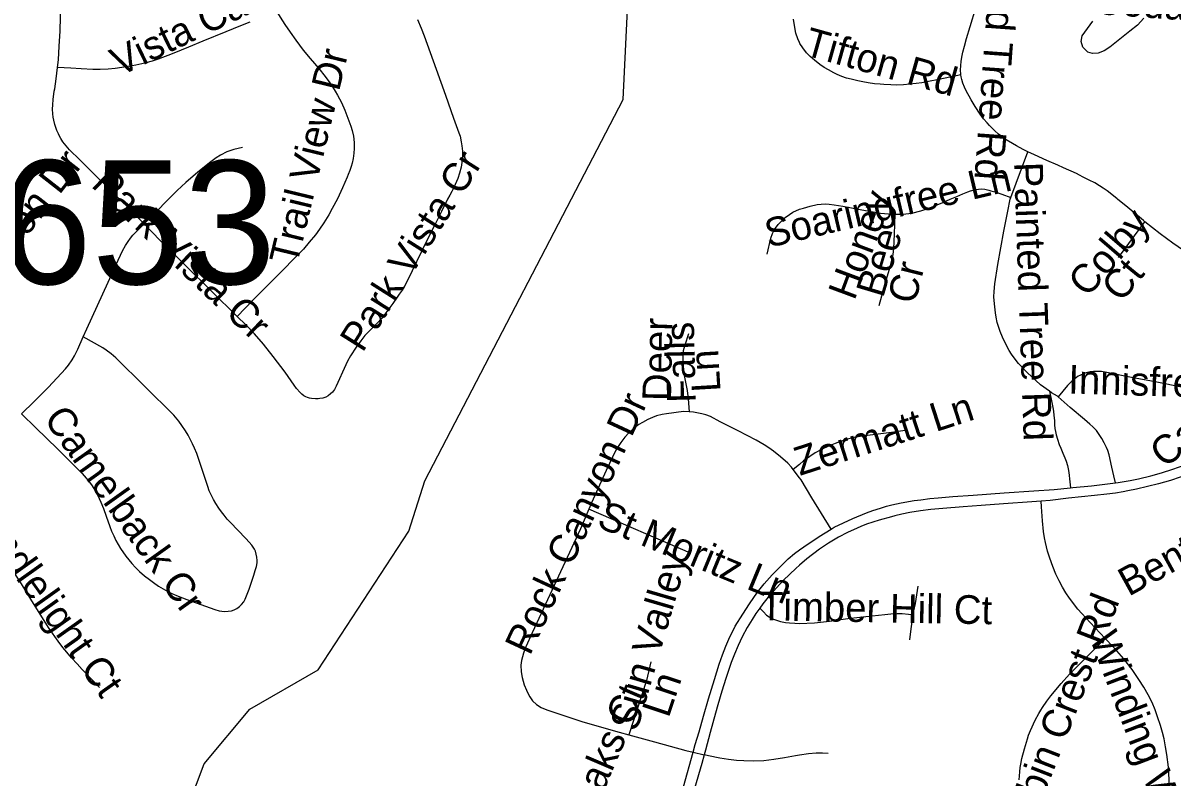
# Model space of a CAD drawing. Extents: x 1383679 to 1536984, y 460658 to 651027.
# Drawn here: x 1441502 to 1445312, y 487151 to 489649 of the extents above; entities that cross this region are included whole.
import ezdxf

# ---------------------------------------------------------------- set-up
doc = ezdxf.new("R2010")
doc.units = 0
for name, color, linetype in [('Exist Hydrographic Creek Single Shore', 7, 'Continuous'), ('Exist Road Non-System Type 51', 7, 'Continuous'), ('Exist Road Non-System Type 51 Label', 7, 'Continuous'), ('Exist Road Primary US Structure Non-Sys NCDOT Number Label', 7, 'Continuous')]:
    doc.layers.add(name, color=color, linetype=linetype)

msp = doc.modelspace()

# ---------------------------------------------------------------- linework, layer by layer
at = {"layer": 'Exist Hydrographic Creek Single Shore'}
msp.add_lwpolyline([(1440714.2, 484403.2), (1441192.2, 484968), (1441297.1, 485235.1), (1441297.1, 485676.3), (1441341, 485777.5), (1441756.5, 486277.7), (1442102.4, 487194.6), (1442253.2, 487375.7), (1442480.2, 487505.7), (1442780.2, 487965.7), (1442833.2, 488132.1), (1443490.2, 489395.8), (1443517.3, 489946.6)], dxfattribs=at)
at = {"layer": 'Exist Road Non-System Type 51'}
for p, q in [((1444774.5, 489071.2), (1444831.6, 489222.1)), ((1445131.9, 488872.3), (1445219.4, 488990.4)), ((1443713.5, 487892.8), (1443376.4, 488038.1)), ((1443722.7, 487233), (1443758.7, 487224.3))]:
    msp.add_line(p, q, dxfattribs=at)
for points in [[(1441616.1, 489501.8), (1441619, 489526.9), (1441622, 489572.1), (1441624.8, 489622.1), (1441625.6, 489669.8), (1441624.7, 489728.7), (1441623.3, 489767.8), (1441622.8, 489805.8), (1441620.1, 489834.7)], [(1444609.1, 489477.5), (1444608.8, 489479.5), (1444608.1, 489493.2), (1444608.8, 489508.6), (1444610.2, 489521.5), (1444612.7, 489535.6), (1444616.3, 489553.1), (1444621.4, 489572.9), (1444628.2, 489597.7), (1444640, 489638.2), (1444696.9, 489824.2), (1444709.2, 489868.5)], [(1442340.8, 489690.1), (1442369.2, 489644.9), (1442386.9, 489619), (1442405.7, 489592.4), (1442430.7, 489559), (1442453.4, 489531.9), (1442482.1, 489499), (1442503.5, 489472.3), (1442518.5, 489451), (1442527.3, 489437.6), (1442535.7, 489423.6), (1442544.1, 489409.8), (1442556.8, 489385.7), (1442568.1, 489360.6), (1442578.7, 489333.6), (1442588.3, 489307.7), (1442592.8, 489292.9), (1442596.6, 489274.5), (1442598.8, 489253.1), (1442599.4, 489233.2), (1442598.6, 489217.7), (1442596.3, 489200.3), (1442592.8, 489184.7), (1442589.3, 489173.8), (1442584.4, 489160.7), (1442579.6, 489147.8), (1442576.1, 489138.5), (1442560.9, 489103.6), (1442543.4, 489066.5), (1442526.5, 489034.2), (1442515.1, 489013.8), (1442498.3, 488987.7), (1442484.6, 488966.7), (1442470.7, 488947.6), (1442450.5, 488922.6), (1442431.2, 488900.2), (1442409.6, 488878), (1442353.5, 488821.5), (1442326, 488794.2), (1442301.4, 488768), (1442265, 488731.7), (1442212, 488677.3)], [(1442254, 489652), (1442222.6, 489639.7), (1442173.9, 489620.1), (1442097.9, 489589.4), (1442050.1, 489569.2), (1442002.1, 489549.4), (1441981.4, 489541.1), (1441964.2, 489534.8), (1441949.5, 489529.4), (1441929.5, 489523.2), (1441909, 489517.7), (1441895.2, 489514.1), (1441875.9, 489509.7), (1441863.7, 489507.4), (1441843.4, 489503.7), (1441828.8, 489501.5), (1441807.2, 489499), (1441784.4, 489496.8), (1441757.5, 489495.6), (1441733.3, 489495.6), (1441694.8, 489497), (1441660.6, 489499.4), (1441616.1, 489501.8)], [(1442809.2, 489660.7), (1442821.2, 489631.8), (1442831.4, 489606.8), (1442871.1, 489496.9), (1442901.9, 489410.7), (1442928, 489334.3), (1442941.8, 489297.6), (1442946, 489285.4), (1442949.9, 489273.9), (1442954.1, 489255.3), (1442956, 489241.8), (1442957.7, 489224.5), (1442958.1, 489209.8), (1442956.8, 489197.2), (1442955.7, 489187.4), (1442953.4, 489171.3), (1442948.3, 489151.6), (1442942.3, 489133.7), (1442934.3, 489114.7), (1442928.6, 489102.4), (1442922.5, 489091.2), (1442916.1, 489079.2), (1442908.8, 489066), (1442888.7, 489025), (1442864, 488976), (1442836.2, 488922.4), (1442775.8, 488795.7), (1442763.6, 488773.3), (1442758.1, 488764.3), (1442748.4, 488750.4), (1442727.2, 488720.3), (1442701.3, 488684.7), (1442689.2, 488670.4), (1442675.5, 488655.1), (1442645.6, 488625.2), (1442634.7, 488613.3), (1442620.8, 488595.7), (1442605.9, 488574.7), (1442587, 488546.6), (1442576.8, 488529.2), (1442571.4, 488516.9), (1442539, 488446.2), (1442534.2, 488435.3), (1442527.6, 488426.3), (1442520.5, 488420.3), (1442513.3, 488414.3), (1442504.9, 488409.3), (1442495.6, 488406.2), (1442485.8, 488404.6), (1442479.4, 488404.3), (1442471.3, 488404.3), (1442458.2, 488405.5), (1442450.7, 488406.6), (1442444.9, 488408.8), (1442438.7, 488411), (1442432.4, 488414), (1442426, 488419.3), (1442419.9, 488425.3), (1442407.9, 488438.6), (1442400.4, 488449), (1442370.5, 488492.7), (1442331.3, 488544.2), (1442298.6, 488585.4), (1442268.9, 488619.2), (1442240.2, 488649.5), (1442212, 488677.3)], [(1444609.1, 489477.5), (1444536.6, 489462), (1444502.3, 489455.4), (1444479.7, 489451.6), (1444460.9, 489448.5), (1444440.7, 489446.2), (1444419, 489444.7), (1444397.6, 489443.7), (1444377.9, 489444), (1444354.5, 489445.1), (1444342, 489446.2), (1444322.9, 489448), (1444302.4, 489450.8), (1444284.8, 489454.1), (1444268.3, 489457.3), (1444246.4, 489462.7), (1444231, 489467), (1444215.2, 489472.4), (1444199.4, 489478.8), (1444188.6, 489483.9), (1444170.6, 489493.6), (1444156.3, 489502.2), (1444141.6, 489512.2), (1444124.3, 489525.9), (1444109.9, 489538.8), (1444098.4, 489550.5), (1444085.6, 489567), (1444076.1, 489581.9), (1444075, 489584.3), (1444069.2, 489596.9), (1444062.6, 489616.2), (1444057.7, 489641.6), (1444054.5, 489661.5)], [(1445216.1, 489665.8), (1445194.2, 489642.4), (1445169.5, 489622.8), (1445103.2, 489569.4), (1445083.8, 489556.7), (1445064.1, 489549.2), (1445045.4, 489548.4), (1445029.6, 489552.9), (1445013.8, 489569.4), (1445007.8, 489588.2), (1445010.8, 489606.3), (1445046.5, 489655.9)], [(1441903.1, 488983.9), (1441855.8, 489032.8), (1441822, 489066), (1441804.8, 489082.9), (1441742.6, 489143.8), (1441732.4, 489153.7), (1441690.3, 489195.8), (1441655.9, 489229.5), (1441639.5, 489248.8), (1441634.2, 489255.9), (1441627.6, 489266.4), (1441623.1, 489274.7), (1441619.4, 489282.2), (1441614.4, 489292.6), (1441611.5, 489299.6), (1441607.1, 489313.3), (1441604, 489327.5), (1441602.2, 489337), (1441600.9, 489348.3), (1441599.6, 489364.3), (1441600.3, 489378.6), (1441601.7, 489395.5), (1441605.6, 489423.8), (1441606.9, 489431.7), (1441611.7, 489464.2), (1441616.1, 489501.8)], [(1444831.6, 489222.1), (1444816.1, 489230), (1444793.4, 489241.9), (1444780.1, 489249.8), (1444760, 489262.7), (1444748.5, 489271), (1444734.5, 489281.4), (1444722.3, 489291.8), (1444710.8, 489302.9), (1444704.3, 489309.4), (1444696.1, 489318.4), (1444684.9, 489331.3), (1444673.1, 489347.4), (1444656.9, 489372.6), (1444644, 489394.8), (1444636.4, 489407.4), (1444628.5, 489422.1), (1444621.4, 489436.5), (1444616, 489450.5), (1444612.4, 489462), (1444610.2, 489470.6), (1444609.1, 489477.5)], [(1442228.8, 489237.1), (1442200.9, 489230.7), (1442177.3, 489222.1), (1442156.7, 489211.8), (1442141.8, 489202.7), (1442119.8, 489185.8), (1442081.3, 489154.9), (1442040.9, 489120.3), (1442012.5, 489094.5), (1441984.3, 489066), (1441971.7, 489053.3), (1441951.5, 489032.7), (1441903.1, 488983.9)], [(1445219.4, 488990.4), (1445214.1, 488994.6), (1445162.3, 489038.4), (1445128.6, 489066), (1445125.8, 489068.3), (1445094.2, 489092.9), (1445081.2, 489102.2), (1445068.6, 489110.1), (1445052.9, 489119.4), (1445034.8, 489129), (1445014.9, 489138.7), (1445002.1, 489145.4), (1444992.7, 489150.1), (1444949.8, 489169.3), (1444930.6, 489178.1), (1444894.6, 489193.8), (1444853.5, 489212.2), (1444831.6, 489222.1)], [(1444391.3, 489015.6), (1444391.4, 489015.6), (1444412.8, 489015.9), (1444427.1, 489016.8), (1444446.7, 489019.5), (1444476.7, 489026.6), (1444501.4, 489034.7), (1444549.3, 489054.3), (1444574.1, 489066), (1444596.3, 489074.8), (1444615.8, 489082.9), (1444632.2, 489089.4), (1444641.8, 489092.9), (1444657.6, 489097.2), (1444667.8, 489098.7), (1444677.7, 489099.3), (1444688.5, 489098.7), (1444697.3, 489096.9), (1444702.5, 489095.5), (1444708.7, 489093.7), (1444721.5, 489089.9), (1444745.2, 489082.3), (1444774.5, 489071.2)], [(1443967.4, 488883.4), (1443979.5, 488936.1), (1443984.8, 488951.7), (1443991.5, 488965.3), (1444003.7, 488981.2), (1444015.7, 488994.1), (1444027.7, 489005.2), (1444041.4, 489015.1), (1444052.6, 489022.1), (1444075, 489032.7), (1444087.9, 489036.3), (1444110.6, 489042.4), (1444133.1, 489047.5), (1444146.9, 489049.2), (1444160.5, 489049.8), (1444173.4, 489049), (1444190, 489047), (1444218.1, 489042.1), (1444281.7, 489029.8), (1444343.1, 489019.7), (1444369.1, 489016.8), (1444391.3, 489015.6)], [(1444902.8, 488428.8), (1444873.4, 488450.7), (1444828.9, 488491.7), (1444800.9, 488520.9), (1444785.5, 488540), (1444777, 488552.1), (1444769.5, 488563.6), (1444759, 488583), (1444747.6, 488608.2), (1444739.6, 488627), (1444734.1, 488643.7), (1444730.2, 488656.5), (1444726.3, 488674.7), (1444724.2, 488688.5), (1444720.5, 488718.8), (1444719, 488742.4), (1444719.5, 488759.2), (1444722.1, 488785.2), (1444731.4, 488849.5), (1444752.2, 488959.4), (1444765.1, 489025.5), (1444772.5, 489066), (1444774.5, 489071.2)], [(1444338.8, 488713.3), (1444360.1, 488789.8), (1444375.7, 488841.1), (1444381.1, 488863.5), (1444384.7, 488882.6), (1444386.9, 488902.5), (1444389.1, 488949.4), (1444391.3, 489015.6)], [(1441701.6, 488609.3), (1441713.2, 488635.9), (1441748.7, 488713.4), (1441783.8, 488790.7), (1441809, 488846.6), (1441824.8, 488880.1), (1441831.6, 488894.4), (1441842, 488912.3), (1441850.3, 488925.7), (1441858, 488936.1), (1441865.7, 488946.3), (1441869.6, 488950.1), (1441903.1, 488983.9)], [(1441903.1, 488983.9), (1441956.5, 488928.7), (1442212, 488677.3)], [(1445876.8, 488552.8), (1445846.9, 488574.5), (1445722.6, 488684.9), (1445681.9, 488720.1), (1445649.3, 488744.1), (1445620.3, 488762.4), (1445594, 488777.2), (1445552.9, 488797.4), (1445505.9, 488818.4), (1445423.1, 488854), (1445402.6, 488864.3), (1445383.1, 488874.5), (1445347, 488896), (1445311.5, 488920.1), (1445269.7, 488950.6), (1445219.4, 488990.4)], [(1443707.2, 488619.7), (1443694.8, 488581.9), (1443689.6, 488563.2), (1443688.4, 488552.2), (1443687.8, 488526.7), (1443689.2, 488506.9), (1443692.7, 488481.2), (1443702.2, 488432), (1443705.7, 488404.1), (1443709.1, 488361.3)], [(1441497.4, 488354), (1441539.1, 488394.7), (1441586.2, 488442.2), (1441643.2, 488502.8), (1441653.1, 488515.6), (1441665, 488532.7), (1441672.9, 488546), (1441683.9, 488568.6), (1441701.6, 488609.3)], [(1441497.4, 488354), (1441544.4, 488308.2), (1441616.2, 488238.4), (1441663.2, 488190.7), (1441697.8, 488156.3), (1441711.3, 488141.1), (1441721.9, 488127.6), (1441731.5, 488115.1), (1441740.4, 488101.6), (1441748.3, 488085.4), (1441753.7, 488073.8), (1441759.6, 488061.2), (1441768.1, 488040.3), (1441777.2, 488015.5), (1441789.2, 487980.5), (1441795, 487965.4), (1441802.3, 487950), (1441809.5, 487934.9), (1441825.2, 487907.8), (1441842.8, 487883.1), (1441862.5, 487858), (1441874.6, 487844.6), (1441887.9, 487831.6), (1441903.9, 487817.7), (1441920.7, 487804.8), (1441934.8, 487794.8), (1441950.6, 487783.4), (1441974.5, 487769.4), (1441994.9, 487758.9), (1442015.6, 487749.9), (1442044.2, 487738.5), (1442137.4, 487706), (1442151.7, 487701.7), (1442160.6, 487699.9), (1442169.9, 487699.6), (1442182.2, 487700.1), (1442192.4, 487701.7), (1442201.7, 487704.6), (1442210.9, 487709.6), (1442219.2, 487715.8), (1442226.2, 487722.3), (1442233.1, 487731), (1442238.3, 487740.2), (1442242.8, 487751), (1442250.8, 487773.6), (1442266.8, 487819.9), (1442271.5, 487835.5), (1442275.2, 487848.6), (1442277.5, 487860.4), (1442277.9, 487868.3), (1442276.7, 487879.1), (1442274.8, 487888.9), (1442272.1, 487899.1), (1442269.4, 487906.1), (1442264.8, 487912.8), (1442260.5, 487918.6), (1442241.6, 487940.2), (1442212.5, 487970.1), (1442190.9, 487992.6), (1442178.7, 488005.7), (1442168.3, 488017.9), (1442159.6, 488030), (1442151.2, 488041.8), (1442141.1, 488057.4), (1442133.6, 488070.1), (1442127.4, 488081.5), (1442119.1, 488099.6), (1442114.5, 488112.9), (1442087.5, 488193), (1442077.5, 488222.3), (1442070.2, 488241), (1442063.8, 488255.2), (1442056.1, 488270.3), (1442048.9, 488283.8), (1442040.3, 488298), (1442028.7, 488316), (1442018.1, 488329.9), (1442001.3, 488350.1), (1441809.6, 488539.8), (1441794.1, 488552.8), (1441777.7, 488564.9), (1441766.5, 488572.5), (1441701.6, 488609.3)], [(1445122, 488125.7), (1445130.2, 488126.7), (1445170.8, 488133.3), (1445198.4, 488139), (1445238.6, 488148.9), (1445274.7, 488158.8), (1445311.8, 488171.1), (1445348.8, 488184.5), (1445407.3, 488205), (1445458.6, 488225.5), (1445494, 488243), (1445526.1, 488260.7), (1445558.2, 488281.2), (1445589.8, 488302.7), (1445640.5, 488336.4), (1445658.2, 488348.7), (1445694.9, 488376.3), (1445718.8, 488396.3), (1445741.1, 488415.5), (1445789.1, 488461.7), (1445850.3, 488526.6), (1445876.8, 488552.8)], [(1445346, 488441.1), (1445252.8, 488459.9), (1445175.2, 488474.5), (1445093, 488491), (1445075.2, 488494), (1445058.5, 488495), (1445048.8, 488494.4), (1445038.1, 488493.1), (1445025, 488489.9), (1445015.9, 488486.8), (1445003.3, 488481.1), (1444998.5, 488478.5), (1444992.1, 488474.6), (1444984.5, 488469), (1444978.1, 488463.6), (1444963.3, 488448.3), (1444931.4, 488410.9)], [(1444931.4, 488410.9), (1444929.8, 488412.4), (1444909.7, 488423.7), (1444902.8, 488428.8)], [(1444902.8, 488428.8), (1444908.3, 488403.1), (1444914, 488375.4), (1444916.1, 488363), (1444917.8, 488349), (1444919.4, 488331.7), (1444920.1, 488317.8), (1444921.2, 488306.1), (1444922.9, 488295.3), (1444925.4, 488284.5), (1444929.3, 488270.1), (1444935.2, 488252.9), (1444940.3, 488240.3), (1444947.8, 488223.8), (1444954, 488208.9), (1444958.4, 488197.5), (1444962.7, 488183.1), (1444965, 488172.2), (1444966.9, 488159.6), (1444970.4, 488129.2), (1444972.9, 488109.2)], [(1445122, 488125.7), (1445116.3, 488148.5), (1445109.6, 488177.5), (1445100.5, 488217.9), (1445096, 488232.9), (1445092.1, 488242.8), (1445084.4, 488258.4), (1445076.2, 488272.8), (1445067.9, 488285.7), (1445058.4, 488298.6), (1445046.9, 488310.7), (1445037.1, 488319.9), (1445019.5, 488335.2), (1444972.1, 488374.7), (1444931.4, 488410.9)], [(1443709.1, 488361.3), (1443690.7, 488361.5), (1443634.2, 488354.2), (1443619.6, 488351.8), (1443601.1, 488347.2), (1443587.9, 488342.4), (1443572.3, 488335.1), (1443554.4, 488325.8), (1443542.6, 488318.7), (1443529.5, 488309.4), (1443509.6, 488291.7), (1443495.6, 488276.5), (1443482.5, 488259.5), (1443466.4, 488233.8), (1443434.1, 488166.6), (1443385.7, 488059.8), (1443376.4, 488038.1)], [(1444053.9, 488169.7), (1444048, 488177.3), (1444035.8, 488190.5), (1444012.2, 488212.1), (1443989.1, 488230), (1443973.1, 488241.7), (1443958, 488251), (1443931.6, 488266.6), (1443871.2, 488297.6), (1443811.7, 488328.1), (1443780, 488345.1), (1443764.6, 488351.3), (1443751, 488354.5), (1443724, 488359.7), (1443710.4, 488361.3), (1443709.1, 488361.3)], [(1444432.3, 488299.6), (1444379.5, 488292.1), (1444317.5, 488284.6), (1444282.1, 488279.9), (1444255.4, 488275.3), (1444234.3, 488270), (1444213.5, 488264.1), (1444193, 488256.3), (1444170.8, 488246.8), (1444148, 488236.5), (1444127.1, 488225.1), (1444108.9, 488213.3), (1444088.4, 488198.3), (1444075, 488186.2), (1444053.9, 488169.7)], [(1444179.4, 487972.5), (1444116.1, 488075.8), (1444080.4, 488135.2), (1444075, 488142.2), (1444053.9, 488169.7)], [(1445438.9, 488181.4), (1445433.2, 488179), (1445391, 488163.2), (1445383.4, 488160.6), (1445335.6, 488143.9), (1445304, 488133.8), (1445264.3, 488122.3), (1445191.7, 488104.7), (1445162.9, 488098.6), (1445147.7, 488095.9), (1445121.7, 488091.9), (1445093.3, 488088.2), (1445052, 488084.1), (1444965.6, 488074.3), (1444905.5, 488067.5), (1444876, 488065.2)], [(1444972.9, 488109.2), (1444980.2, 488109.9), (1445042.6, 488115.7), (1445122, 488125.7)], [(1441755.8, 487446.9), (1441722.1, 487481.9), (1441697.9, 487506.9), (1441681.6, 487525.3), (1441662.8, 487545.9), (1441646.8, 487564.8), (1441633.9, 487580), (1441617.9, 487601), (1441588.6, 487643.1), (1441558.4, 487690.3), (1441528, 487740.4), (1441497.2, 487790.6), (1441448.8, 487866.3), (1441415.4, 487922.3), (1441394.6, 487954.6), (1441382.4, 487971.8), (1441363, 487996.9), (1441337.7, 488025.2), (1441313.2, 488052.4), (1441255.3, 488107)], [(1444179.4, 487972.5), (1444190, 487979), (1444251, 488007.2), (1444296.5, 488025.8), (1444317.6, 488033.9), (1444342.8, 488042.1), (1444363.3, 488048.3), (1444381, 488052.5), (1444411.5, 488058.9), (1444454.3, 488066.6), (1444476.9, 488069.8), (1444506.7, 488073.6), (1444534, 488076.3), (1444582.9, 488080.3), (1444650, 488085.2), (1444753.4, 488093), (1444851, 488099.6), (1444918.5, 488103.8), (1444972.9, 488109.2)], [(1444876, 488065.2), (1444844.3, 488062.7), (1444750.5, 488056.1), (1444676.9, 488050.5), (1444617.1, 488045.8), (1444550, 488040.7), (1444510.2, 488036.8), (1444475.5, 488032.5), (1444440.1, 488026.9), (1444414.2, 488021.9), (1444390.8, 488016.5), (1444379.2, 488013.4), (1444338.9, 488002.1), (1444296.5, 487988.1), (1444278.1, 487981), (1444265.7, 487975.9), (1444234.1, 487961.4), (1444203.7, 487945.8), (1444170.5, 487925.2), (1444141.2, 487905.5), (1444099.5, 487874.1), (1444075, 487852.9), (1444062.7, 487842.2), (1444022, 487803.1), (1443998.3, 487778.2), (1443970.7, 487746.3), (1443953.2, 487724.1), (1443943.2, 487710.4)], [(1445088, 487609.8), (1445037.7, 487663), (1444997.1, 487707.4), (1444969.3, 487742.9), (1444957.4, 487760.7), (1444946, 487779.7), (1444934.6, 487800.5), (1444923.8, 487823.3), (1444914.3, 487848.2), (1444903.8, 487876.5), (1444897, 487898.8), (1444889.8, 487928.1), (1444886.7, 487943.4), (1444883.4, 487964), (1444879.4, 487999.2), (1444876.4, 488046.2), (1444876, 488065.2)], [(1443376.4, 488038.1), (1443348.8, 487973.7), (1443253.6, 487769.1), (1443219, 487692.2), (1443188.5, 487628.5), (1443168.1, 487582.1), (1443160.6, 487561.5), (1443153.2, 487536.8), (1443151.5, 487521.9), (1443152.5, 487499), (1443155.6, 487480.1), (1443162.5, 487456), (1443170.4, 487438.1), (1443173.3, 487431.2), (1443180.8, 487416.3), (1443190.1, 487403.6), (1443203.8, 487391.1), (1443218.6, 487381.4), (1443237.3, 487373.2), (1443357.3, 487333.8), (1443477.7, 487299.1), (1443508.9, 487290.6)], [(1443722.7, 487233), (1443722.8, 487233.3), (1443728.8, 487259), (1443742.4, 487301), (1443756.7, 487352.5), (1443773.1, 487409.5), (1443792.9, 487473.8), (1443809.1, 487524.6), (1443819.5, 487555.2), (1443830.7, 487584.2), (1443841.1, 487607.9), (1443862.1, 487650.1), (1443887.1, 487690.9), (1443909.1, 487724.9), (1443936.1, 487763.8), (1443957.8, 487791.2), (1443984, 487821.1), (1444037.6, 487873.2), (1444058.6, 487891.2), (1444075, 487903.4), (1444089.2, 487914), (1444139.8, 487948.3), (1444179.4, 487972.5)], [(1444451.4, 487688.2), (1444452.9, 487697.2), (1444458.6, 487726), (1444468.2, 487782.9)], [(1443943.2, 487710.4), (1443930.3, 487692.6), (1443917.9, 487672.7), (1443901.8, 487646.3), (1443885, 487615), (1443871.2, 487586.3), (1443859.3, 487558.1), (1443848.3, 487530.7), (1443831.1, 487477.6), (1443817, 487435.3), (1443803.9, 487389.6), (1443796.6, 487362.8), (1443778.9, 487297.9), (1443762.9, 487239.9), (1443758.7, 487224.3)], [(1443943.2, 487710.4), (1443955.7, 487697.7), (1443965.8, 487687.6), (1443974.4, 487681.2), (1443985, 487674.9), (1443995.1, 487671.2), (1444011.3, 487666.6), (1444027.9, 487663.1), (1444041.5, 487661.4), (1444058.9, 487660.4), (1444075, 487659.4), (1444124.7, 487661.9), (1444174.6, 487666.8), (1444235.1, 487675.6), (1444294.4, 487682.8), (1444358, 487689.8), (1444377.3, 487691.9), (1444398.6, 487692.9), (1444415, 487692.6), (1444435.4, 487690.2), (1444451.4, 487688.2)], [(1444440, 487604.8), (1444445, 487641.6), (1444449, 487674.3), (1444451.4, 487688.2)], [(1444802.8, 487141.6), (1444804.5, 487168.4), (1444806.1, 487182.2), (1444807.7, 487193.7), (1444811.4, 487211.8), (1444819.9, 487244.6), (1444826.4, 487266.5), (1444829.7, 487276.8), (1444834, 487289.6), (1444840.3, 487304.6), (1444855.8, 487339.2), (1444867.4, 487361), (1444873.9, 487372.2), (1444879.4, 487380.7), (1444894.1, 487401.8), (1444907.2, 487419.3), (1444942.2, 487461.1), (1444969.7, 487491.7), (1445088, 487609.8)], [(1445302.3, 486936.3), (1445303.3, 486969.1), (1445302.4, 487036.2), (1445301.6, 487098.6), (1445297.2, 487183), (1445292, 487225.8), (1445287.6, 487251), (1445282.7, 487277.3), (1445277.5, 487298), (1445270.7, 487321.7), (1445261.5, 487350.1), (1445252.8, 487373), (1445242.9, 487397.2), (1445229.5, 487423.4), (1445215.7, 487448.3), (1445199.5, 487474.3), (1445176.8, 487506.9), (1445149, 487542.8), (1445126.7, 487568.7), (1445092.3, 487605.3), (1445088, 487609.8)], [(1443581.8, 487532.3), (1443567.7, 487471.1), (1443508.9, 487290.6)], [(1443508.9, 487290.6), (1443594.4, 487267.3), (1443698.5, 487238.8), (1443722.7, 487233)], [(1443594.1, 486786.3), (1443603.3, 486809.1), (1443609.8, 486829.4), (1443627.5, 486890.7), (1443640.9, 486938), (1443659, 487006.2), (1443675.5, 487067.2), (1443690.7, 487118), (1443722.7, 487233)], [(1443758.7, 487224.3), (1443751.1, 487196), (1443727.1, 487112.9), (1443701.9, 487031.6), (1443694.4, 487010.6), (1443670.6, 486935.1), (1443654.2, 486871.4), (1443633.9, 486799.9), (1443625.1, 486774.5)], [(1444170.1, 487228.6), (1444150.8, 487230), (1444130.3, 487230.1), (1444104.4, 487227.4), (1444075, 487223.7), (1444061.8, 487221.4), (1444025.3, 487213.9), (1443989.7, 487208.8), (1443956.5, 487204.8), (1443923.3, 487203.3), (1443890, 487204), (1443865.5, 487206), (1443840, 487209), (1443810.3, 487213.5), (1443772.9, 487220.8), (1443758.7, 487224.3)]]:
    msp.add_lwpolyline(points, dxfattribs=at)

# ---------------------------------------------------------------- texts
at = {"layer": 'Exist Road Non-System Type 51 Label'}
for s, rotation, p in [('Painted Tree Rd', 265.8606, (1444721.2, 490054.8)), ('Vista Canyon Dr', 25.7941, (1441822, 489471.1)), ('Cedar View Rd', 355.822, (1445049.4, 489680)), ('Tifton Rd', 344.3248, (1444084.9, 489544.6)), ('Trail View Dr', 76.418, (1442409.5, 488843.7)), ('Rimrock Canyon Dr', 51.9621, (1441021.6, 488310.1)), ('Park Vista Cr', 57.6698, (1442626.8, 488554.4)), ('Park Vista Cr', 316.2734, (1441724.4, 489109.3)), ('Soaringfree Ln', 13.2584, (1443972.4, 488904.4)), ('Painted Tree Rd', 271.9888, (1444785.6, 489187.3)), ('Honey', 69.5798, (1444256.6, 488727.1)), ('Colby', 49.2681, (1445029, 488736.9)), ('Bee', 73.2865, (1444351.4, 488735.7)), ('Cr', 75.9637, (1444457.6, 488714.3)), ('Ct', 50.7105, (1445141.3, 488720.2)), ('Deer', 89.0982, (1443649.1, 488395.9)), ('Falls', 91.4319, (1443731.2, 488391.8)), ('Carmel Rd', 39.2069, (1445285.2, 488171.6)), ('Ln', 93.3663, (1443813.3, 488428.5)), ('Innisfree Pl', 358.2108, (1444964.2, 488422)), ('Rock Canyon Dr', 65.0656, (1443181.3, 487550.1)), ('Zermatt Ln', 17.8793, (1444075.6, 488148.3)), ('Camelback Cr', 305.4993, (1441567.8, 488337.9)), ('Bent Twig Ct', 28.8431, (1445165.3, 487747.6)), ('Candlelight Ct', 305.4379, (1441300, 488057.3)), ('St Moritz Ln', 337.5213, (1443399.1, 487981.2)), ('Sun Valley', 73.686, (1443535.8, 487298.2)), ('Timber Hill Ct', 359.0096, (1443943.2, 487670.2)), ('Robin Crest Rd', 68.7536, (1444821.6, 486925)), ('Winding Way Rd', 290.8919, (1445034.9, 487612.1)), ('Ln', 71.5651, (1443640.9, 487343.6)), ('Carmel Oaks Ct', 66.8107, (1443211.2, 486600.7))]:
    msp.add_text(s, height=95, rotation=rotation, dxfattribs=at).set_placement(p)
at = {"layer": 'Exist Road Primary US Structure Non-Sys NCDOT Number Label'}
msp.add_text('H653', height=410.1, dxfattribs=at).set_placement((1441028.7, 488784))

doc.saveas('drawing.dxf')
